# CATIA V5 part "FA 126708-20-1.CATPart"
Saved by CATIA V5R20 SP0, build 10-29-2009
Part number: FA 126708-20-1
Revision: ANY
Definition: UNKNOWN
Nomenclature: FA 126708-20-1
Source: Unknown
Bounding box of the stored display mesh (mm): x -5.85 to 5.85, y -10 to 10, z -6 to 6
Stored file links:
  C:\Users\Utente\Desktop\IO LAVORO\3D X SITO CF\CUMSA\3D files FA\FA 126708-20\FA 126708-20-1.CATPart
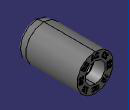
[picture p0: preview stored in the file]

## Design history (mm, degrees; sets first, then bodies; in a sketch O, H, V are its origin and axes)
Body1 "Cortar-Extruir5" (main body)
  Solid1: solid without history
